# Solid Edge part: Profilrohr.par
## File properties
Username: bmolnar
Dokumentum tartalom típus: 0
Author: bmolnar
Last saved by: bmolnar
Revision: 82
Sűrűség: 0,000 kg/m^3
Pontosság: 0,990
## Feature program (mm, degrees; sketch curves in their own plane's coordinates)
base feature "unnamed BaseFeature 1"
thread "unnamed Thread 1"
thread "Menet_2"  ThreadDepth = 7.5 mm
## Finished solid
Body 1: solid body, 121 faces, 264 edges, 166 vertices.
  Faces by surface: plane 78, cylinder 29, cone 10, torus 4
  Edges by curve: line 188, circle 68, curve on surface 7, intersection 1
Bounding box of the edges (mm; curved faces can reach further): 65.000 x 70.000 x 79.500, from (-32.5, -32.5, 0) to (32.5, 37.5, 79.5).
Cylindrical faces by radius (mm): R1.375 x2, R3.4 x4, R4.283 x4, R5.5 x8, R25 x1, R25.9 x2, R26.1 x2, R27.6 x2, R43 x4
Conical faces (half-angle, radius in mm at the cone's reference point): 30 deg R25.325 x2, 30 deg R26.1887 x2, 45 deg R4.533 x2, 45 deg R26.25 x2, 45 deg R26.35 x2
Toroidal faces (ring radius, tube radius in mm): R27.4 r0.2 x4
Planar faces by outward normal: +x 9, +y 11, +z 8, -x 9, -y 9, -z 8, oblique 24
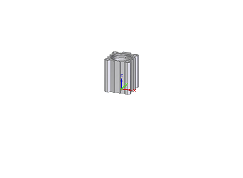
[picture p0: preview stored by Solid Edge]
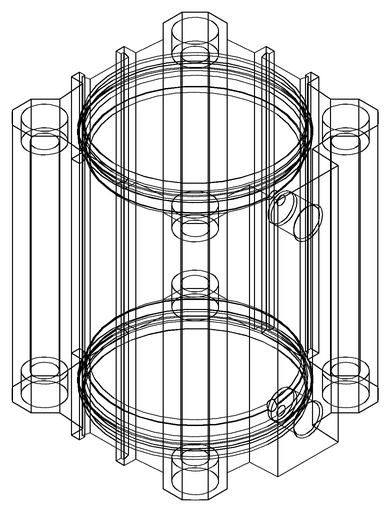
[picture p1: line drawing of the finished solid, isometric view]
